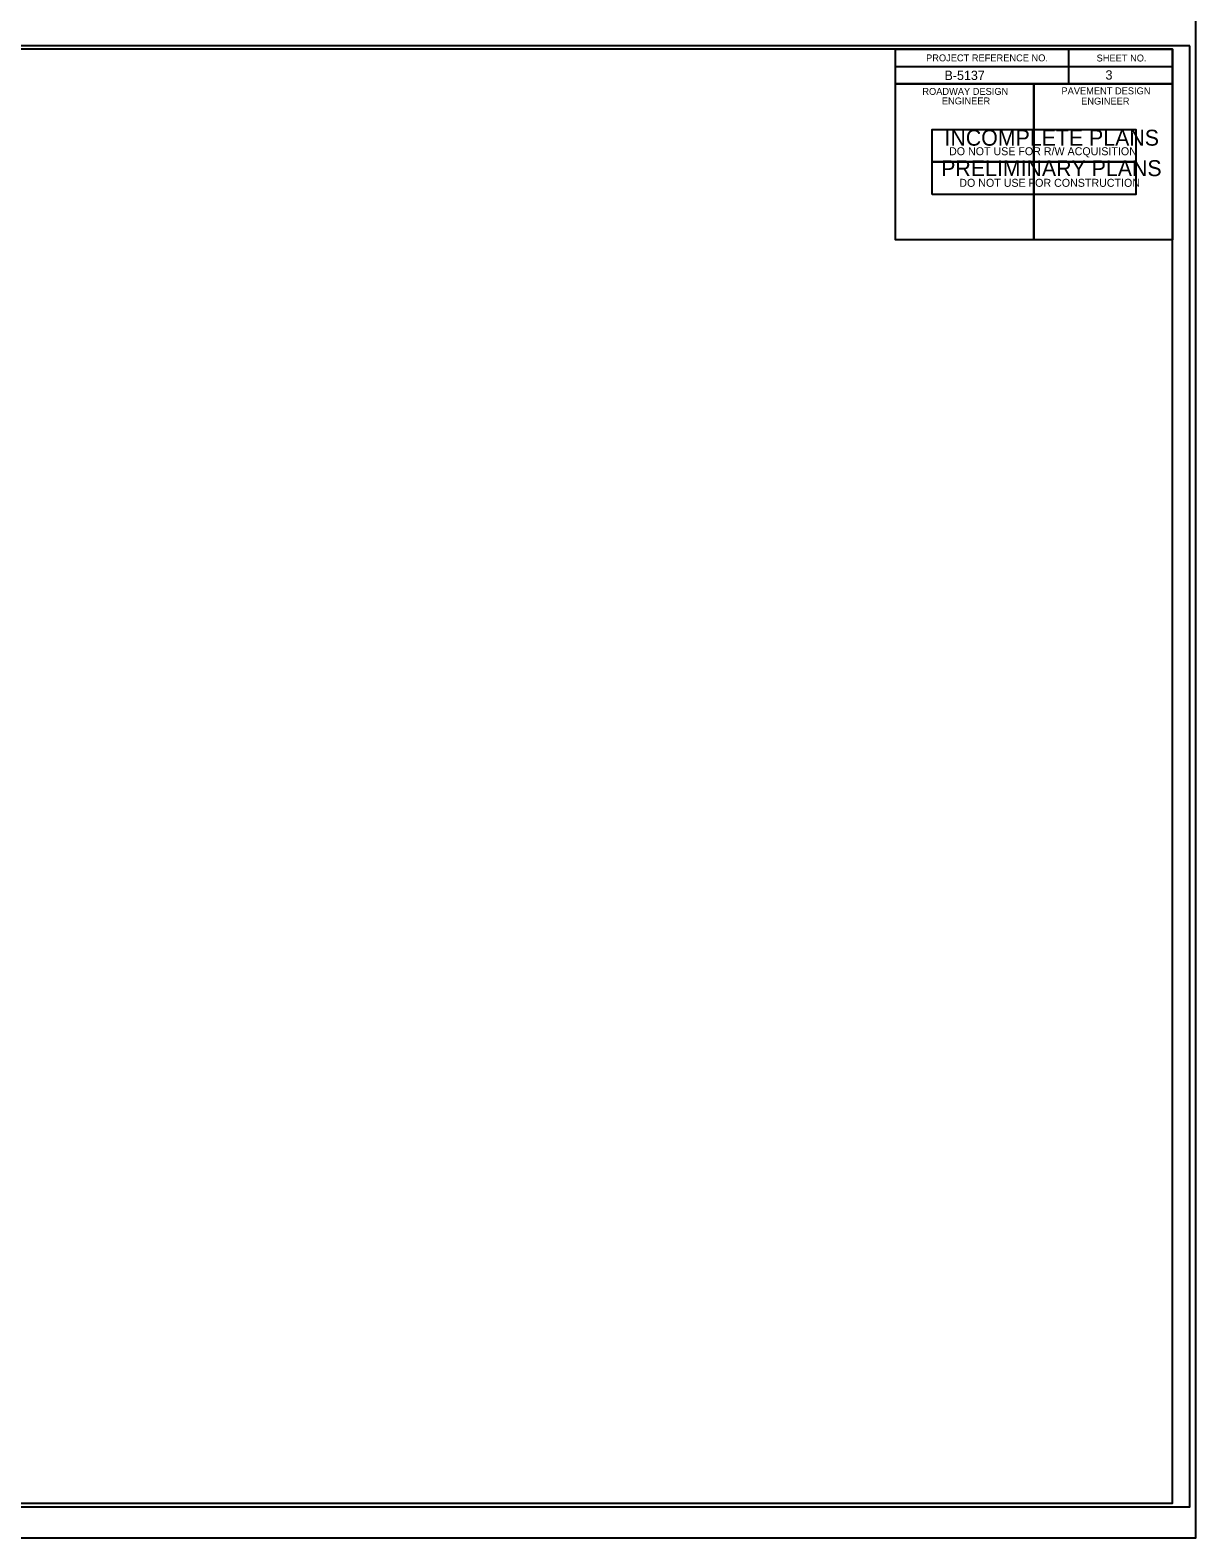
# Model space of a CAD drawing. Extents: x 1664524 to 1666208, y 587901 to 592296.
# Drawn here: x 1665366 to 1666208, y 587901 to 588990 of the extents above; entities that cross this region are included whole.
import ezdxf

# ---------------------------------------------------------------- set-up
doc = ezdxf.new("R2010")
doc.units = 0
for name, color, linetype in [('Prop Horizontal Alignment', 7, 'Continuous'), ('Prop Horizontal Alignment Curve and Spiral Data', 7, 'Continuous'), ('Prop Horizontal Alignment Direction Label', 7, 'Continuous'), ('Prop Horizontal Alignment Tick Large', 7, 'Continuous'), ('Prop Horizontal Alignment Tick Small', 7, 'Continuous'), ('Sheet Cutting Line CELL', 7, 'Continuous'), ('Sheet Typical CELL', 7, 'Continuous')]:
    doc.layers.add(name, color=color, linetype=linetype)

msp = doc.modelspace()

# ---------------------------------------------------------------- linework, layer by layer
at = {"layer": 'Prop Horizontal Alignment Curve and Spiral Data'}
msp.add_lwpolyline([(1666017.3, 588895), (1666017.3, 588918.5), (1666164.3, 588918.5), (1666164.3, 588895)], close=True, dxfattribs=at)
at = {"layer": 'Prop Horizontal Alignment Direction Label'}
msp.add_lwpolyline([(1666017.3, 588871.5), (1666017.3, 588895), (1666164.3, 588895), (1666164.3, 588871.5)], close=True, dxfattribs=at)
at = {"layer": 'Prop Horizontal Alignment Tick Large'}
msp.add_lwpolyline([(1666203.3, 588978.9), (1664536.8, 588978.9), (1664536.8, 587923.8), (1666203.3, 587923.8)], close=True, dxfattribs=at)
at = {"layer": 'Prop Horizontal Alignment Tick Small'}
msp.add_lwpolyline([(1666207.8, 589001.3), (1664523.8, 589001.3), (1664523.8, 587901.3), (1666207.8, 587901.3)], close=True, dxfattribs=at)
at = {"layer": 'Sheet Cutting Line CELL'}
msp.add_line((1664523.8, 587901.3), (1666207.8, 587901.3), dxfattribs=at)
at = {"layer": 'Sheet Typical CELL'}
for p, q in [((1666115.8, 588976.3), (1666115.8, 588951.3)), ((1665990.7, 588963.8), (1666190.8, 588963.8)), ((1666090.8, 588951.3), (1666090.8, 588838.8))]:
    msp.add_line(p, q, dxfattribs=at)
for points in [[(1666190.8, 588976.3), (1664690.8, 588976.3), (1664690.8, 587926.3), (1666190.8, 587926.3)], [(1665990.7, 588976.3), (1666190.8, 588976.3), (1666190.8, 588951.3), (1665990.7, 588951.3)], [(1665990.7, 588951.3), (1666090.8, 588951.3), (1666090.8, 588838.8), (1665990.7, 588838.8)], [(1666090.8, 588951.3), (1666190.8, 588951.3), (1666190.8, 588838.8), (1666090.8, 588838.8)]]:
    msp.add_lwpolyline(points, close=True, dxfattribs=at)

# ---------------------------------------------------------------- texts
at = {"layer": 'Prop Horizontal Alignment'}
for s, p in [('B-5137   ', (1666026.2, 588954.1)), ('3  ', (1666142.5, 588954.4))]:
    msp.add_text(s, height=6.75, dxfattribs=at).set_placement(p)
at = {"layer": 'Prop Horizontal Alignment Curve and Spiral Data'}
for s, height, p in [('INCOMPLETE PLANS', 11.52, (1666026.2, 588906.7)), ('DO NOT USE FOR R/W ACQUISITION', 5.76, (1666029.5, 588899.8))]:
    msp.add_text(s, height=height, dxfattribs=at).set_placement(p)
at = {"layer": 'Prop Horizontal Alignment Direction Label'}
for s, height, p in [('PRELIMINARY PLANS', 11.52, (1666023.8, 588884.7)), ('DO NOT USE FOR CONSTRUCTION', 5.76, (1666036.9, 588877)), ('DO NOT USE FOR CONSTRUCTION', 5.76, (1666036.9, 588877))]:
    msp.add_text(s, height=height, dxfattribs=at).set_placement(p)
at = {"layer": 'Sheet Typical CELL'}
for s, p in [('PROJECT REFERENCE NO.', (1666012.9, 588967.6)), ('SHEET NO.', (1666136.1, 588967.5)), ('ROADWAY DESIGN', (1666010.2, 588943.4)), ('ENGINEER', (1666024.3, 588936.5)), ('PAVEMENT DESIGN', (1666110.7, 588943.8)), ('ENGINEER', (1666124.9, 588936.4))]:
    msp.add_text(s, height=5, dxfattribs=at).set_placement(p)

doc.saveas('drawing.dxf')
